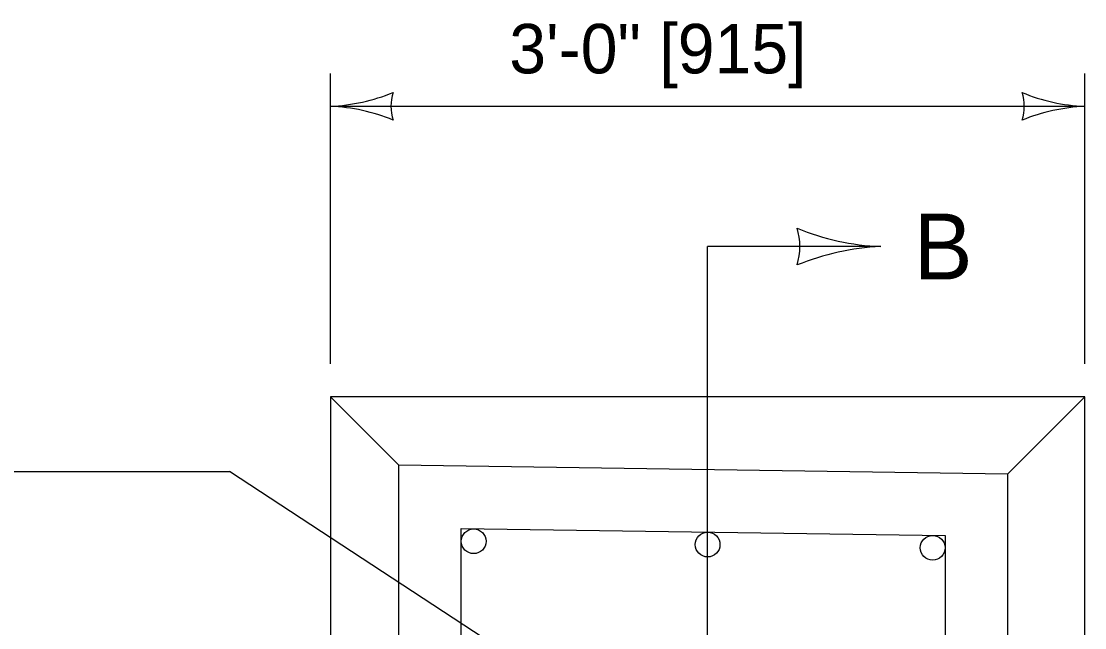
# Model space of a CAD drawing. Extents: x 49991.4 to 50021, y 49987.6 to 50011.4.
# Drawn here: x 50009.364 to 50010.654, y 49993.053 to 49993.789 of the extents above; entities that cross this region are included whole.
import ezdxf

# ---------------------------------------------------------------- set-up
doc = ezdxf.new("R2010")
doc.units = 0
for name, color, linetype in [('Level 1', 7, 'Continuous'), ('Level 2', 7, 'Continuous'), ('Level 3', 7, 'Continuous'), ('Level 6', 7, 'Continuous'), ('Level 7', 7, 'Continuous'), ('S_BOT_RW_TTL_Sheet_No_DF', 7, 'Continuous')]:
    doc.layers.add(name, color=color, linetype=linetype)

msp = doc.modelspace()

# ---------------------------------------------------------------- linework, layer by layer
at = {"layer": 'Level 1'}
for p, q in [((50010.6541, 49993.3332), (50009.7391, 49993.3332)), ((50009.7391, 49993.3332), (50009.7391, 49992.4182)), ((50009.8216, 49993.2507), (50009.7391, 49993.3332)), ((50010.5609, 49993.24), (50010.6541, 49993.3332)), ((50010.6541, 49992.4182), (50010.6541, 49993.3332)), ((50009.8216, 49993.2507), (50009.8216, 49992.5007)), ((50009.8216, 49993.2507), (50010.5609, 49993.24)), ((50010.5609, 49992.5114), (50010.5609, 49993.24)), ((50009.8978, 49993.1733), (50010.4846, 49993.1649)), ((50009.8978, 49992.5781), (50009.8978, 49993.1733)), ((50010.4846, 49993.1649), (50010.4846, 49992.5866))]:
    msp.add_line(p, q, dxfattribs=at)
at = {"layer": 'Level 3'}
for p, q in [((50009.7391, 49993.3732), (50009.7391, 49993.7257)), ((50010.6541, 49993.3732), (50010.6541, 49993.7257)), ((50009.7391, 49993.6857), (50010.6541, 49993.6857)), ((50009.2768, 49993.2428), (50009.6168, 49993.2428)), ((50010.0216, 49992.9772), (50009.6168, 49993.2428))]:
    msp.add_line(p, q, dxfattribs=at)
for centre, radius, start, end in [((50009.7276, 49993.9184), 0.233, 272.8273, 292.0772), ((50009.8673, 49993.6857), 0.0548, 162.1388, 197.8612), ((50010.6632, 49993.9078), 0.2223, 247.456, 267.6395), ((50010.5259, 49993.6857), 0.0548, 342.1388, 17.8612), ((50009.7299, 49993.4636), 0.2223, 67.456, 87.6395), ((50010.6656, 49993.453), 0.233, 92.8273, 112.0772)]:
    msp.add_arc(centre, radius, start, end, dxfattribs=at)
at = {"layer": 'Level 6'}
for p in [(50010.1966, 49992.1832), (50010.4066, 49993.5156)]:
    msp.add_line(p, (50010.1966, 49993.5156), dxfattribs=at)
for centre, radius, start, end in [((50010.4188, 49993.8117), 0.2964, 247.456, 267.6395), ((50010.2356, 49993.5156), 0.073, 342.1388, 17.8612), ((50010.4219, 49993.2053), 0.3107, 92.8273, 112.0772)]:
    msp.add_arc(centre, radius, start, end, dxfattribs=at)
at = {"layer": 'Level 7'}
for centre in [(50009.9128, 49993.158), (50010.1966, 49993.154), (50010.4696, 49993.1501)]:
    msp.add_circle(centre, 0.015, dxfattribs=at)
at = {"layer": 'S_BOT_RW_TTL_Sheet_No_DF'}
msp.add_line((50010.6541, 49993.6857), (50010.6541, 49993.7257), dxfattribs=at)

# ---------------------------------------------------------------- texts
at = {"layer": 'Level 2'}
for s, height, p in [('3\'-0" [915]', 0.06, (50009.956, 49993.7257)), ('B', 0.08, (50010.4466, 49993.4756))]:
    msp.add_text(s, height=height, dxfattribs=at).set_placement(p)

doc.saveas('drawing.dxf')
